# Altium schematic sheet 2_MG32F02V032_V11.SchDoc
size 330 x 231 mm; PageSetup: Record=PageOptions|CenterHorizontal=True|CenterVertical=True|PrintScale=0.90|XCorrection=1.00|YCorrection=1.00|PrintKind=0|BorderSize=5000000|LeftOffset=0|BottomOffset=0|Orientation=2|PaperLength=1000|PaperWidth=1000|Scale=100|PaperSource=7|PrintQuality=-4|MediaType=1|DitherType=10|PaperKind=A4 (210 x 297 mm)|PrintScaleMode=1
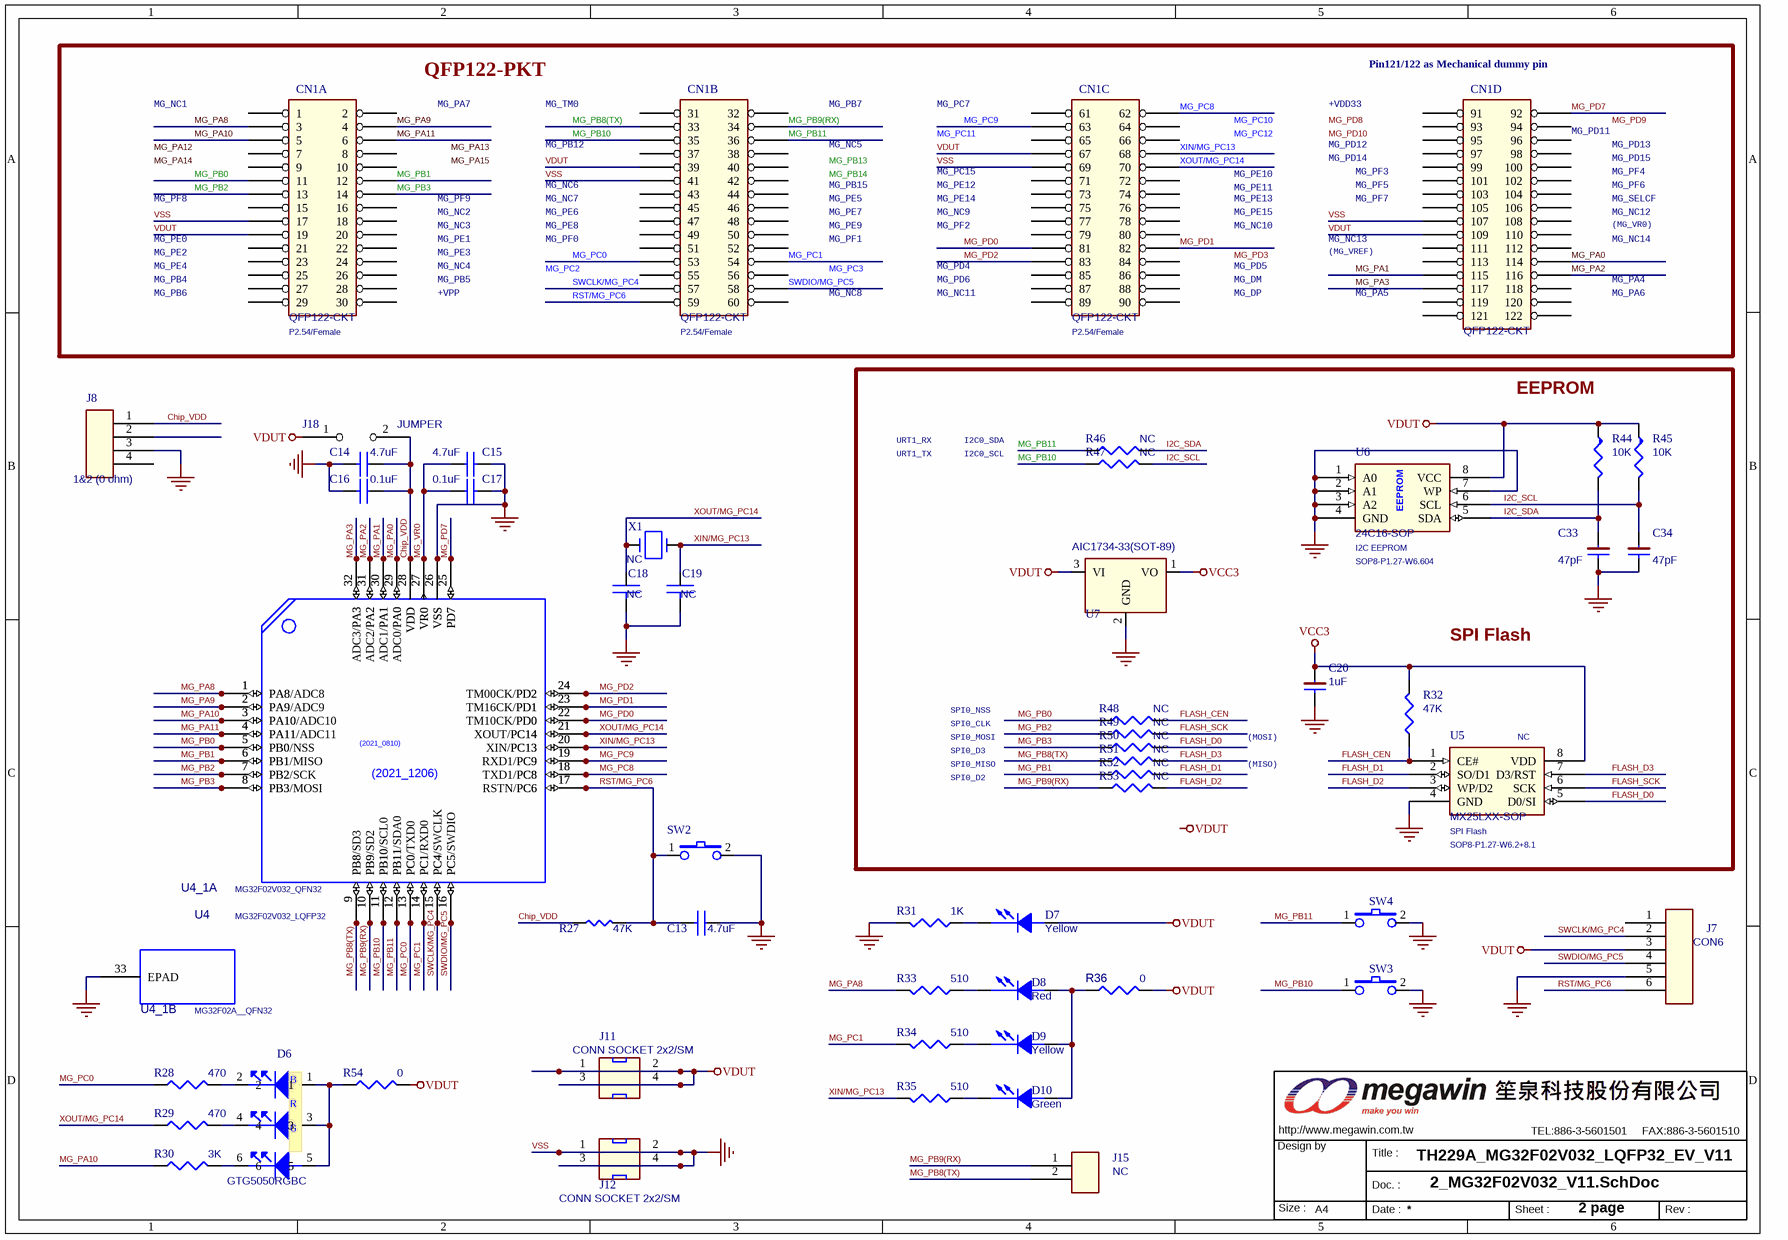
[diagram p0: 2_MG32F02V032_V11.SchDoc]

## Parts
C13  4.7uF  [0805C]
C14  4.7uF  [0805C]
C15  4.7uF  [0805C]
C16  0.1uF  [0603C]
C17  0.1uF  [0603C]
C18  NC  [0603C]
C19  NC  [0603C]
C20  1uF  [0603C]
C33  47pF  [0603C]
C34  47pF  [0603C]
CN1  QFP122-CKT  Package: P2.54/Female  [QFP122-P2.54-CKT]  (parts A,B,C,D of 4)
D6  GTG5050RGBC  [LED6P_RGB_SMD_50X50]
D7  Yellow  [0805D]
D8  Red  [LED38+0805]
D9  Yellow  [LED38+0805]
D10  Green  [LED38+0805]
J7  CON6  [PS6P254]
J8  1&2 (0 ohm)  [PS4P254]
J11  CONN SOCKET 2x2/SM  [PS2X2P254]
J12  CONN SOCKET 2x2/SM  [PS2X2P254]
J15  NC  [PS2P254]
J18  JUMPER  [PS2P254]
MW1  OrgAddr3: TEL:886-3-5601501     FAX:886-3-5601510  [MEGAWIN_3.4]  (hidden comment: MW-A4)  (graphical)
R27  47K  [0603R]
R28  470  [0603R]
R29  470  [0603R]
R30  3K  [0603R]
R31  1K  [0603R]
R32  47K  [0603R]
R33  510  [0603R]
R34  510  [0603R]
R35  510  [0603R]
R36  0  [PS2p254+0603]
R44  10K  [0603R]
R45  10K  [0603R]
R46  NC  [0603R]
R47  NC  [0603R]
R48  NC  [0603R]
R49  NC  [0603R]
R50  NC  [0603R]
R51  NC  [0603R]
R52  NC  [0603R]
R53  NC  [0603R]
R54  0  [PS2p254+0603]
SW2  SW TACT-SPST  [SW_T_2P]  (value not drawn)
SW3  SW TACT-SPST  [SW_T_2P]  (value not drawn)
SW4  SW TACT-SPST  [SW_T_2P]  (value not drawn)
U4  MG32F02V032_LQFP32  [QFP32-P0.8-Z8.8X8.8]
U4_1  MG32F02V032_QFN32  [QFN32-P0.5-Z5X5-TPAD]  (parts A,B of 2)
U5  MX25LXX-SOP  Function: SPI Flash  Assembly: NC  Package: SOP8-P1.27-W6.2+8.1  [SO8_208P127]
U6  24C16-SOP  Function: I2C EEPROM  Package: SOP8-P1.27-W6.604  [SO8_150P127]
U7  AIC1734-33(SOT-89)  [SOT89]
X1  NC  [X49U]

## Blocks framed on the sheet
QFP122-PKT: CN1

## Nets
VCC3: C20.1 R32.2 U5.8(VDD) U7.1(VO)
VDUT: CN1.19 CN1.39 CN1.67 CN1.109 D7.1(ANODE) J7.3 J11.1 J11.2 J11.3 J11.4 J18.1 R36.2 R44.1 R45.1 R54.2 U6.8(VCC) U7.3(VI)
VSS: C13.1 C14.2 C15.2 C16.2 C17.2 C18.2 C19.2 C20.2 C33.2 C34.2 CN1.17 CN1.41 CN1.69 CN1.107 J7.5 J8.3 J12.1 J12.2 J12.3 J12.4 R31.1 SW2.2 SW3.2 SW4.2 U4.26(VSS) U4_1.26(VSS) U4_1.33(EPAD) U5.4(GND) U6.1(A0) U6.2(A1) U6.3(A2) U6.4(GND) U6.7(WP) U7.2(GND)  [also labelled GND_POWER]
Chip_VDD: C14.1 C16.1 J8.1 J18.2 R27.1 U4.28(VDD) U4_1.28(VDD)
FLASH_CEN: R32.1 R48.2 U5.1(CE#)
FLASH_D0: R50.2 U5.5(D0/SI)
FLASH_D1: R52.2 U5.2(SO/D1)
FLASH_D2: R53.2 U5.3(WP/D2)
FLASH_D3: R51.2 U5.7(D3/RST)
FLASH_SCK: R49.2 U5.6(SCK)
I2C_SCL: C34.1 R45.2 R47.2 U6.6(SCL)
I2C_SDA: C33.1 R44.2 R46.2 U6.5(SDA)
MG_PA0: CN1.114 U4.29(ADC0/PA0) U4_1.29(PA0)
MG_PA1: CN1.115 U4.30(ADC1/PA1) U4_1.30(PA1)
MG_PA2: CN1.116 U4.31(ADC2/PA2) U4_1.31(PA2)
MG_PA3: CN1.117 U4.32(ADC3/PA3) U4_1.32(PA3)
MG_PA8: CN1.3 R33.1 U4.1(PA8/ADC8) U4_1.1(PA8)
MG_PA9: CN1.4 U4.2(PA9/ADC9) U4_1.2(PA9)
MG_PA10: CN1.5 R30.1 U4.3(PA10/ADC10) U4_1.3(PA10)
MG_PA11: CN1.6 U4.4(PA11/ADC11) U4_1.4(PA11)
MG_PB0: CN1.11 R48.1 U4.5(PB0/NSS) U4_1.5(PB0)
MG_PB1: CN1.12 R52.1 U4.6(PB1/MISO) U4_1.6(PB1)
MG_PB2: CN1.13 R49.1 U4.7(PB2/SCK) U4_1.7(PB2)
MG_PB3: CN1.14 R50.1 U4.8(PB3/MOSI) U4_1.8(PB3)
MG_PB8(TX): CN1.33 J15.2 R51.1 U4.9(PB8/SD3) U4_1.9(PB8)
MG_PB9(RX): CN1.34 J15.1 R53.1 U4.10(PB9/SD2) U4_1.10(PB9)
MG_PB10: CN1.35 R47.1 SW3.1 U4.11(PB10/SCL0) U4_1.11(PB10)
MG_PB11: CN1.36 R46.1 SW4.1 U4.12(PB11/SDA0) U4_1.12(PB11)
MG_PC0: CN1.53 R28.1 U4.13(PC0/TXD0) U4_1.13(PC0)
MG_PC1: CN1.54 R34.1 U4.14(PC1/RXD0) U4_1.14(PC1)
MG_PC8: CN1.62 U4.18(TXD1/PC8) U4_1.18(PC8)
MG_PC9: CN1.63 U4.19(RXD1/PC9) U4_1.19(PC9)
MG_PD0: CN1.81 U4.22(TM10CK/PD0) U4_1.22(PD0)
MG_PD1: CN1.82 U4.23(TM16CK/PD1) U4_1.23(PD1)
MG_PD2: CN1.83 U4.24(TM00CK/PD2) U4_1.24(PD2)
MG_PD7: CN1.92 U4.25(PD7) U4_1.25(PD7)
MG_VR0: C15.1 C17.1 U4.27(VR0) U4_1.27(VR0)
RST/MG_PC6: C13.2 CN1.59 J7.6 R27.2 SW2.1 U4.17(RSTN/PC6) U4_1.17(PC6)
SWCLK/MG_PC4: CN1.57 J7.2 U4.15(PC4/SWCLK) U4_1.15(PC4)
SWDIO/MG_PC5: CN1.58 J7.4 U4.16(PC5/SWDIO) U4_1.16(PC5)
XIN/MG_PC13: C19.1 CN1.68 R35.1 U4.20(XIN/PC13) U4_1.20(PC13) X1.2
XOUT/MG_PC14: C18.1 CN1.70 R29.1 U4.21(XOUT/PC14) U4_1.21(PC14) X1.1
NetD6_1: D6.1 D6.3 D6.5 R54.1
NetD6_2: D6.2 R28.2
NetD6_4: D6.4 R29.2
NetD6_6: D6.6 R30.2
NetD7_2: D7.2(CATHODE) R31.2
NetD8_1: D8.1(ANODE) D9.1(ANODE) D10.1(ANODE) R36.1
NetD8_2: D8.2(CATHODE) R33.2
NetD9_2: D9.2(CATHODE) R34.2
NetD10_2: D10.2(CATHODE) R35.2

Not connected (* = marked no-connect by the designer): CN1 1 2 7 8 9 10 15 16 18 20 21 22 23 24 25 26 27 28 29 30 31 32 37 38 40 42 43 44 45 46 47 48 49 50 51 52 55 56 60 61 64 65 66 71 72 73 74 75 76 77 78 79 80 84 85 86 87 88 89 90 91 93 94 95 96 97 98 99 100 101 102 103 104 105 106 108 110 111 112 113 118 119 120 121 122; J7 1; J8 2 4

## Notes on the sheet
- MG_NC1
- MG_PA7
- MG_TM0
- MG_PB7
- MG_PC7
- +VDD33
- (near CN1) Pin121/122 as Mechanical dummy pin
- MG_PB12
- MG_NC5
- MG_PC15
- MG_PE10
- MG_PD12
- MG_PD14
- MG_PF3
- (near CN1) MG_PD11
- MG_PF4
- MG_PD13
- MG_PD15
- MG_PF8
- MG_PE0
- MG_PF9
- MG_NC2
- MG_NC3
- MG_PE1
- MG_NC6
- MG_NC7
- MG_PE6
- MG_PF0
- MG_PE8
- MG_PE5
- MG_PE7
- MG_PF1
- MG_PE9
- MG_PB15
- MG_NC9
- MG_PF2
- MG_PE12
- MG_PE14
- MG_PE11
- MG_NC10
- MG_PE13
- MG_PE15
- MG_NC13
- MG_PF5
- MG_PF7
- MG_NC12
- MG_NC14
- MG_PF6
- MG_SELCF
- (MG_VR0)
- MG_PE4
- MG_PE2
- MG_PB4
- MG_PB6
- +VPP
- MG_NC4
- MG_PE3
- MG_PB5
- MG_NC8
- MG_NC11
- MG_PD4
- MG_PD6
- MG_DM
- MG_DP
- MG_PD5
- (MG_VREF)
- MG_PA5
- MG_PA4
- MG_PA6
- URT1_RX
- I2C0_SDA
- EEPROM
- URT1_TX
- I2C0_SCL
- SPI Flash
- SPI0_NSS
- SPI0_CLK
- SPI0_MOSI
- SPI0_MISO
- SPI0_D3
- SPI0_D2
- (MOSI)
- (MISO)
- TH229A_MG32F02V032_LQFP32_EV_V11
- 2 page
- Labels drawn without touching a wire or pin: MG_PA12, MG_PA13, MG_PA14, MG_PA15, MG_PB13, MG_PB14, MG_PC2, MG_PC3, MG_PC10, MG_PC11, MG_PC12, MG_PD3, MG_PD8, MG_PD9, MG_PD10, VDUT

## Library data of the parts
C13-C17 = CAP NP_Dup1
C18 C19 = C NP_Dup1
C20 C33 C34 = CAP-NP
D6 = LED_GTG5050RGBC
D7-D10 = LED
J7 = CON6_Dup1
J8 = CON4
J15 = CON2
MW1 = MW_A4_2
R27 = R_Dup4
R28-R36 R46-R54 = R_Dup5
R44 R45 = R: 2ND PART FIELD: SMD_0805
U4 = IC32_MG32F02V032: Designator: A; OriginalSymbolOrigin: (0,0); SWAP_INFO: (S1+S2); SPLIT_INST: TRUE
U4_1 = IC-MG32F02V032-QFN32_0: Designator: B; SPLIT_INST: TRUE; SWAP_INFO: (S1+S2); OriginalSymbolOrigin: (0,0)
U5 = ICM-25LXX
U6 = ICM-24CXX: 1ST PART FIELD: OSD Record Buffer; 2ND PART FIELD: SOP_8PIN
U7 = AIC1722-33
X1 = CRYSTAL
